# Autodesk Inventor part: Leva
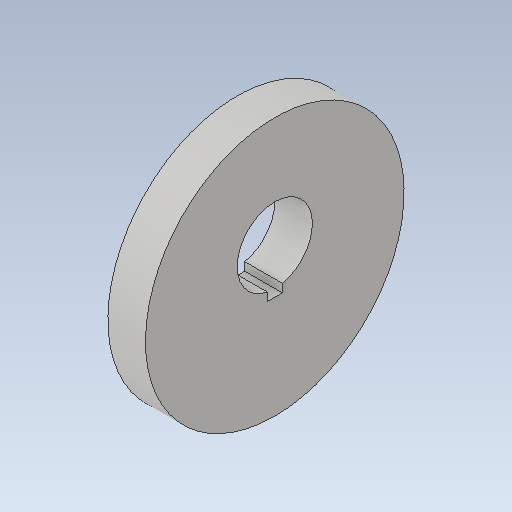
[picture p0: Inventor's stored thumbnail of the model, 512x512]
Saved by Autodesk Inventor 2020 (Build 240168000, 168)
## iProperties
Created: 2019-09
Part Number: Leva
Material: Generic
Document SubType Name: Modeling
Designer: user
Density: 1 g/cm^3
Appearance: Default
Author: user
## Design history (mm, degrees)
sketch "Sketch1"
  geometry: L1 (-4.899, 1)-(-6, 1); L2 (-6, 1)-(-6, -1); L3 (-6, -1)-(-4.899, -1); A1 r 17.202 centre (-2.5, 0) between (14.702, 0) and (-19.702, 0); A2 r 17.202 centre (-2.5, 0) between (-19.702, 0) and (14.702, 0); A3 r 5 centre (0, 0) between (-4.899, -1) and (-4.899, 1); 1 further point
  constraints: 6 end point, 6 point on circle, 3 centre point, 1 coincident, 1 concentric, 1 horizontal, 1 parallel, 1 perpendicular
  dimensions: "d2" = 10 diameter of A3
extrude "Extrusion1" new body sketch "Sketch1" distance "d3" = 5; taper "d4" = 0 deg
body "Solid1"
